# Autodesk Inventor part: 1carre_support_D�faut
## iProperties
Created: 2011-01
Part Number: 1carre_support_D�faut
Document SubType Name: Modeling
Designer: eric
Density: 1 g/cm^3
Mass: 13.663 g
Surface Area: 278.946 cm^2
Volume: 13.663 cm^3
Author: eric
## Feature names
1. Base1
